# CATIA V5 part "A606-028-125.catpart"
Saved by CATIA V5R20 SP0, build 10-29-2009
Part number: A606-028-125
Source: Unknown
Property "ARTICLENO": "A606-028-125"
Property "BOMINFO": "A606-028-125"
Property "CODE": "A606-028-125"
Property "HOLES": "2"
Property "L": "125.000"
Property "L1": "25.000"
Property "L2": "75.000"
Property "LINA": "A606-028-125"
Property "NB": "A606-028-125"
Property "NBSYN": "$CODE."
Property "NN": "A606"
Property "NT": "Wear Plates, self-lubricating"
Property "SCREW": "2xM6"
Property "SUPPLIER": "CF"
Property "W": "28.000"
Bounding box of the stored display mesh (mm): x -14 to 14, y -5 to 5, z -62.5 to 62.5
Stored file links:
  C:\Users\Utente\Desktop\3D files A606\A606-028-125.catpart
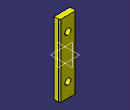
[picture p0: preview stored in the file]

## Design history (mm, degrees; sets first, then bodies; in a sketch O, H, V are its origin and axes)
Body1 "Geometry.1" (main body)
  Solid1 "A606-028-125.catpart": solid without history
